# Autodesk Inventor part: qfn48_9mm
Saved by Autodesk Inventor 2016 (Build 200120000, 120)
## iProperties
Created: 2018-05
Part Number: qfn48_9mm
Material: Generic
Document SubType Name: Modeling
Designer: Administrator
Appearance: Generic
Title: qfn48_9mm v3
Author: Administrator
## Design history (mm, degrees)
feature "Body1"
feature "Body64"
feature "Body65"
feature "Body66"
feature "Body67"
feature "Body68"
feature "Body69"
feature "Body70"
feature "Body71"
feature "Body72"
feature "Body73"
feature "Body74"
feature "Body75"
feature "Body103"
feature "Body104"
feature "Body105"
feature "Body85"
feature "Body86"
feature "Body87"
feature "Body88"
feature "Body89"
feature "Body90"
feature "Body109"
feature "Body110"
feature "Body111"
feature "Body106"
feature "Body107"
feature "Body108"
feature "Body91"
feature "Body92"
feature "Body93"
feature "Body94"
feature "Body95"
feature "Body96"
feature "Body100"
feature "Body101"
feature "Body102"
feature "Body76"
feature "Body77"
feature "Body78"
feature "Body97"
feature "Body98"
feature "Body99"
feature "Body82"
feature "Body83"
feature "Body84"
feature "Body79"
feature "Body80"
feature "Body81"
body "Solid1"
body "Solid2"
body "Solid3"
body "Solid4"
body "Solid5"
body "Solid6"
body "Solid7"
body "Solid8"
body "Solid9"
body "Solid10"
body "Solid11"
body "Solid12"
body "Solid13"
body "Solid14"
body "Solid15"
body "Solid16"
body "Solid17"
body "Solid18"
body "Solid19"
body "Solid20"
body "Solid21"
body "Solid22"
body "Solid23"
body "Solid24"
body "Solid25"
body "Solid26"
body "Solid27"
body "Solid28"
body "Solid29"
body "Solid30"
body "Solid31"
body "Solid32"
body "Solid33"
body "Solid34"
body "Solid35"
body "Solid36"
body "Solid37"
body "Solid38"
body "Solid39"
body "Solid40"
body "Solid41"
body "Solid42"
body "Solid43"
body "Solid44"
body "Solid45"
body "Solid46"
body "Solid47"
body "Solid48"
body "Solid49"
